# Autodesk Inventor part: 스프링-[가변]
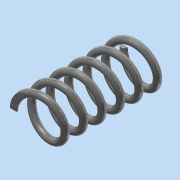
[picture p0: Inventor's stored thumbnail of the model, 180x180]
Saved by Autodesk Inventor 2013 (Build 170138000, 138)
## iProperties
Created: 2415-07
Part Number: 스프링-[가변]
Material: 강철, 탄소
Document SubType Name: Modeling
Designer: Administrator
Mass: 11.5033 g
Surface Area: 23.7278 cm^2
Volume: 1.46166 cm^3
Density: 7.87 g/cm^3
Author: Administrator
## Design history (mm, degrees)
sketch "스케치1"
  geometry: L1 (0, 0)-(-8, 0); L2 (-8, 0)-(-8, 42); L3 (-8, 42)-(0, 42); L4 (0, 42)-(0, 0); C1 r 1.25 at (-8, 0)
  constraints: 8 end point, 2 parallel, 1 centre point, 1 coincident, 1 horizontal, 1 perpendicular
  dimensions: "d1" = 42 distance of L1.end L2.end (derived); "d2" = 2.5 diameter of C1; "d3" = 16 diameter of L2 L4
feature "코일1" sketch "스케치1" pitch "d4" = 10; turns "d6" = 6; dims "d5" = 42 (= d1), "d7" = 0, angle "d8" = 90 deg, angle "d9" = 90 deg, "d10" = 0, "d11" = 0
sketch "스케치2"
  geometry: L1 (9.25, 0)-(6.75, 0) reference; 1 further point
  constraints: 1 horizontal alignment
extrude "돌출1" cut sketch "스케치2" stored distance "d12" = 10; taper "d13" = 0 deg
node "작업 평면1"
sketch "스케치3"
  geometry: L1 (6.75, 0)-(9.25, 0) reference; 1 further point
  constraints: 1 horizontal alignment
extrude "돌출2" cut sketch "스케치3" stored distance "d15" = 10; taper "d16" = 0 deg
node "솔리드1"
node "절단 모서리 투영1"
node "절단 모서리 투영2"
other parameters: "d14" = 42 (= d1)
